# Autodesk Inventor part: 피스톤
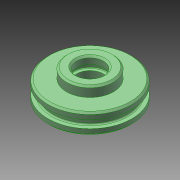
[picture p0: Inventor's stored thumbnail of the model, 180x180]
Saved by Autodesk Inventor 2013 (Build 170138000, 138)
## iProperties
Created: 2023-03
Part Number: 피스톤
Material: 강철, 연강
Document SubType Name: Modeling
Designer: mdu-01
Density: 1 g/cm^3
Author: mdu-01
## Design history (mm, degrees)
sketch "스케치1"
  geometry: L1 (0, 0)-(13, 0); L2 (14, 1)-(14, 6); L3 (14, 6)-(24, 6); L4 (25, 7)-(25, 9.65); L5 (25, 9.65)-(22.8, 9.65); L6 (22, 10.45)-(22, 13.55); L7 (22.8, 14.35)-(25, 14.35); L8 (25, 14.35)-(25, 17); L9 (24, 18)-(14, 18); L10 (14, 18)-(14, 23); L11 (13, 24)-(9, 24); L12 (8, 12)-(0, 12); L13 (0, 12)-(0, 0); L14 (22, 12)-(25, 12); L15 (9, 24)-(8, 23); L16 (14, 23)-(13, 24); L17 (25, 17)-(24, 18); L18 (24, 6)-(25, 7); L19 (13, 0)-(14, 1); L20 (8, 19.6)-(9.6, 19.6); L21 (10, 19.2)-(10, 16.8); L22 (9.6, 16.4)-(8, 16.4); L23 (8, 23)-(8, 19.6); L24 (8, 16.4)-(8, 12); A1 r 0.8 centre (22.8, 10.45) between (22, 10.45) and (22.8, 9.65); A2 r 0.8 centre (22.8, 13.55) between (22.8, 14.35) and (22, 13.55); A3 r 0.4 centre (9.6, 19.2) between (10, 19.2) and (9.6, 19.6); A4 r 0.4 centre (9.6, 16.8) between (9.6, 16.4) and (10, 16.8); 6 further points
  constraints: 48 end point, 11 parallel, 11 point on line, 8 perpendicular, 8 point on circle, 8 tangent, 4 centre point, 3 collinear, 2 equal radius, 2 midpoint, 1 horizontal, 1 other
  dimensions: "d0" = 50 diameter of L4 L13; "d2" = 0.8 radius of A1; "d3" = 24 distance between parallel lines of L11 L1; "d4" = 6 distance between parallel lines of L9 L11; "d5" = 4.7 distance between parallel lines of L5 L7; "d6" = 6 distance between parallel lines of L3 L1; "d7" = 44 diameter of L6 L13; "d8" = 28 diameter of L2 L13; "d10" = 12 distance between parallel lines of L12 L11; "d11" = 1 distance of L11.end point (8, 24); "d12" = 1 distance of L15.end point (8, 24) (= d11); "d13" = 1 distance of L10.end point (14, 24) (= d11); "d14" = 1 distance of L11.start point (14, 24) (= d13); "d15" = 1 distance of L8.end point (25, 18) (= d11); "d16" = 1 distance of L9.start point (25, 18) (= d15); "d17" = 1 distance of L3.end point (25, 6) (= d11); "d18" = 1 distance of L4.start point (25, 6) (= d17); "d19" = 1 distance of L1.end point (14, 0) (= d11); "d20" = 1 distance of L2.start point (14, 0) (= d19); "d31" = 16 diameter of L23 L13; "d32" = 0.4 radius of A3; "d33" = 6 distance from line of point (10, 18) L11; "d34" = 3.2 distance between parallel lines of L22 L20; "d35" = 20 diameter of L21 L13
revolve "회전1" sketch "스케치1" stored, may be unused: angle "d21" = 90 deg
hole "구멍1" diameter "d24" = 6.6; stored, may be unused: countersink angle "d28" = 90 deg, drill point angle "d30" = 118 deg; dims "d25" = 6, "d26" = 11, "d27" = 8, "d29" = 8, "d36" = 10, "d37" = 10
node "솔리드1"
other parameters: "d9" = 16
